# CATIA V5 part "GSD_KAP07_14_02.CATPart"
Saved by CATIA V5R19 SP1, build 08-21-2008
Part number: GSD_KAP07_14_02
Definition: Beispielmodell für die Funktion Eckenverrundung / EdgeFillet - Verrundung begrenzen.
Description: CATIA V5 Flächenmodellierung  Copyright (c) 2009 Maik Hertha IT Consultants
Bounding box of the stored display mesh (mm): x -56.661 to 55.861, y -41.128 to 65.964, z -10 to 30
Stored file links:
  \GSD_BUCH_UEBUNG\GSD_KAP07_14_02.CATPart
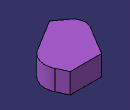
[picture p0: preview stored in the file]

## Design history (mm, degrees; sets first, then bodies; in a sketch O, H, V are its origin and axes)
AxisSystem1 "Absolute Axis System": origin (0, 0, 0), X (1, 0, 0), Y (0, 1, 0), Z (0, 0, 1)
Set1 "Edge Support"
  Plane1: type Equation, A 0, B 0, C 1, Length -10
  Point1: type OnPlane, Support Plane1, Direction (1, 0, 0), H 10, V 10
  Sketch1 on Plane1, origin (10, 10, -10), H (0, 1, 0), V (-1, 0, 0)
    line L1 (-51.1279, 33.3631) -> (-33.587, 56.515)
    arc A1 centre (-13.1715, 41.0472) radius 25.6134 from (-33.587, 56.515) to (0.0896, 62.9604) cw
    line L2 (0.0896, 62.9604) -> (55.9639, 29.1473)
    line L3 (55.9639, 29.1473) -> (55.9639, -32.6844)
    line L4 (55.9639, -32.6844) -> (35.6076, -42.197)
    arc A2 centre (19.1105, -6.8942) radius 38.9672 from (35.6076, -42.197) to (-11.5309, -30.968) cw
    line L5 (-11.5309, -30.968) -> (-51.1279, 33.3631)
    curve C1
    construction line L6 (-0.9087, -48.1015) -> (-25.9518, -8.5836)
    angle L5 L6 = 0.75
    tangency: A1 L1, L2 A1, A2 L4, L6 A2
    vertical: L3 V
  Split1: ToCut Plane1, Cutting Sketch1.C1
  Extrude1: Lim1 40, Lim2 0, Element1 Split1, Direction Plane1
Set2 "Edge 1"
  DatumSurface1: linked copy from another document
Body1 (main body)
